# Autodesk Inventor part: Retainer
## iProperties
Created: 2002-01
Part Number: Retainer
Document SubType Name: Modeling
Designer: ***
Control State: 0
Master: False
Checked Out: False
Shininess: 20.0
Length Units: 11269
Angle Units: 11279
Time Units: 11290
Mass Units: 11283
Length Display Precision: 3
Angle Display Precision: 2
Density: 0.0
Volumn: 0.0
Area: 0.0
PropertySet Name: Model Information
Author: ***
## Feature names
1. Extrusion1
